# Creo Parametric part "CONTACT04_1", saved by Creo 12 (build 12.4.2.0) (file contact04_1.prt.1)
Units: Custom; MM, KILOGRAM, SECS

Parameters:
  PTC_WM_ITERATION = "0"
  PTC_WM_VERSION = "-.0"
  PTC_WM_LIFECYCLE_STATE = "In Work"
  PTC_WM_LIFECYCLE = "MO_CADDocument"
  PTC_WM_CREATED_BY = "Maximilian Roepper (Z0017RMS: MO)"
  PTC_WM_CREATED_ON = "18-Sep-26 11:36:42 AM"
  PTC_WM_MODIFIED_BY = "Maximilian Roepper (Z0017RMS: MO)"
  PTC_WM_MODIFIED_ON = "18-Sep-26 11:36:46 AM"
  PDMLINKNUMBER = "PDM000071454960"
  PTC_WM_NAME = "contact04_1.prt"
  PTC_WM_NUMBER = "PDM000071454960"

Other parameters: WEIGHT, WEIGHT_FACTOR, WEIGHT_ADD, _MASS_TEMP, _DIFF_TEMP, MC_ERRORS, SUPPLIER

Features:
  1. coordinate system
  2. datum plane "PRT_YZ"
  3. datum plane "PRT_XY"
  4. datum plane "PRT_XZ"
  5. coordinate system
  6. datum axis
  7. datum axis
  8. datum axis
  9. coordinate system
  10. imported feature

Other named items: PRT, SIEMENS_MO, DRW_VIEW_ORG, PRT_X, PRT_Y, PRT_Z, CS0, ROUGH_GROB

Layers: 00_STD_CSYS-KSYS, 01_STD_PLANES-EBENEN, 02_STD_AXES-ACHSEN, 03_STD_CSYS-KSYS, 24_IMPORT_FEAT-IMPORT_KE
